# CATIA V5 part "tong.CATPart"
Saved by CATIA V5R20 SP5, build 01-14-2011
Part number: 桶
Material "Zinc": density 7100 kg/m3, Young's modulus 9.7e+10 Pa, Poisson ratio 0.25, thermal expansion 3.12e-05 1/K
Bounding box of the stored display mesh (mm): x -336.462 to 100, y -100 to 100, z 0 to 1058.242
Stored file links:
  E:\3D工程制图作业\choushui  2.CATPart
  D:\CATIA20\win_b64\startup\materials\Catalog.CATMaterial
  D:\CATIA20\win_b64\startup\materials\birch.jpg
  D:\CATIA20\win_b64\startup\materials\brown_fabric_01.jpg
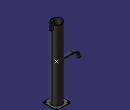
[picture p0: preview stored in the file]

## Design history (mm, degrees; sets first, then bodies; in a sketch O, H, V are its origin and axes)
Set1
  Sketch1 on xy-plane, origin (0, 0, 0), H (1, 0, 0), V (0, 1, 0)
    line L1 (100, 100) -> (100, -100)
    line L2 (100, -100) -> (-100, -100)
    line L3 (-100, -100) -> (-100, 100)
    line L4 (-100, 100) -> (100, 100)
    length L1 = 200
    length L4 = 200
    vertical: L1 V, L3 V
    horizontal: L2 H, L4 H
    equidistance: L1 L3 O, L2 L4 O
Body1 (main body), material "Zinc"
  Pad1: profile Sketch1, direction (0, 0, 1), length 5
  Plane1: type Offset, RefPlane xy-plane, Offset 5
  Sketch2 on Plane1, origin (0, 0, 5), H (1, 0, 0), V (0, 1, 0)
    circle A1 centre (0, 0) radius 70
    radius A1 = 70
  Pad2: profile Sketch2, direction (0, 0, 1), length 1000
  Sketch3 on end face of Pad2, origin (0, 0, 1005), H (1, 0, 0), V (0, 1, 0)
    point P1 (0, 0)
  Hole1: placed by Sketch3, at (0, 0, 1005) direction (0, 0, -1), diameter 130, through (limit type 3)
  Plane2: type Offset, RefPlane Plane1, Offset 500
  Sketch4 on Plane2, origin (0, 0, 505), H (1, 0, 0), V (0, 1, 0)
    point P1 (0, 0)
    coincidence: P1 O
  Plane3: type OffsetPt, RefPlane zx-plane, RefPoint Sketch4
  Body2
    Sketch5 on Plane3, origin (0, 0, 0), H (-1, 0, 0), V (0, 0, 1)
      circle A1 centre (0, 55.0069) radius 1.5
      point P1 (0, 55.0069)
      radius A1 = 1.5
      coincidence: P1 V
    Pad3: profile Sketch5, direction (0, 1, 0), length 30
  Remove1: tool Body2
  Sketch6 on end face of Pad1, origin (-7.2642, 7.8023, 5), H (1, 0, 0), V (0, 1, 0)
    point P1 (-72.7358, 72.1977)
    reference projected line E1 (-92.7358, 92.1977) -> (-92.7358, -107.8023) from edge [face of Pad1 from Sketch1.L3 | end face of Pad1]
    reference projected line E2 (107.2642, 92.1977) -> (-92.7358, 92.1977) from edge [face of Pad1 from Sketch1.L4 | end face of Pad1]
    distance E1 P1 = 20
    distance E2 P1 = 20
  Hole2: placed by Sketch6, at (-80, 80, 5) direction (0, 0, -1), diameter 20, through (limit type 3)
  Sketch7 on zx-plane, origin (0, 0, 0), H (-1, 0, 0), V (0, 0, 1)
    point P1 (7, 1000)
    reference projected line E1 through (0, 0) direction (0, 1) from axis of face of Pad2 from Sketch2.A1
    reference projected line E2 (-70, 1005) -> (70, 1005) from edge [face of Pad2 from Sketch2.A1 | end face of Pad2]
    distance P1 E1 = 7
    distance P1 E2 = 5
  RectPattern1: of Hole2, direction 1 instances 2, spacing 160, along end face of Pad1, direction 2 instances 2, spacing 160, along end face of Pad1 reversed
  Sketch8 on Plane3, origin (0, 0, 0), H (-1, 0, 0), V (0, 0, 1)
    point P1 (0, 509.3928)
    line L1 (0, 509.3928) -> (213.4707, 509.3928)
    arc A1 centre (213.4707, 406.2352) radius 103.1576 from (213.4707, 509.3928) to (316.5702, 409.6977) cw
    point P4 (316.5702, 409.6977)
    point P5 (213.4707, 509.3928)
    coincidence: P1 V, P5 A1, P5 L1
    horizontal: L1 H
    tangency: A1 L1
  Plane4: type Normal, Curve Sketch8, RefPoint Sketch8.P4
  Sketch9 on Plane4, origin (13.3871, 0, 398.6164), H (0, 1, 0), V (-0.9994, 0, 0.0336)
    circle A1 centre (0, 330.0467) radius 20
    point P1 (0, 330.0467)
    radius A1 = 20
    coincidence: P1 V
  Rib1: profile Sketch9, centre curve Sketch8, thin wall 2
  Plane5: type Offset, RefPlane yz-plane, Offset 70
  Sketch10 on Plane5, origin (70, 0, 0), H (0, 1, 0), V (0, 0, 1)
    line L1 (21.9006, 1058.2415) -> (21.9006, 943.5108)
    line L2 (21.9006, 943.5108) -> (0, 943.5108)
    line L3 (0, 943.5108) -> (0, 1058.2415)
    line L4 (0, 1058.2415) -> (21.9006, 1058.2415)
    reference projected line E1 through (0, 0) direction (0, 1) from axis of face of Pad2 from Sketch2.A1
    reference projected line E2 through (0, 0) direction (0, 1) from axis of face of Pad2 from Sketch2.A1
    distance E1 L1 = 21.9006
    distance E2 L3 = 0
    vertical: L1 V, L3 V
    horizontal: L2 H, L4 H
  Pad4: profile Sketch10, direction (1, 0, 0), length 30, mirrored extent
  Body3
    Sketch11 on xy-plane, origin (0, 0, 0), H (1, 0, 0), V (0, 1, 0)
      circle A1 centre (0, 0) radius 65
      radius A1 = 65
    Pad5: profile Sketch11, direction (0, 0, 1), length 2000
  Remove2: tool Body3
  Sketch12 on face of Pad4 from Sketch10.L3, origin (0, 0, 0), H (1, 0, 0), V (0, 0, 1)
    circle A1 centre (83.8907, 1046.4016) radius 5
    radius A1 = 5
  Pad6: profile Sketch12, direction (0, -1, 0), length 10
